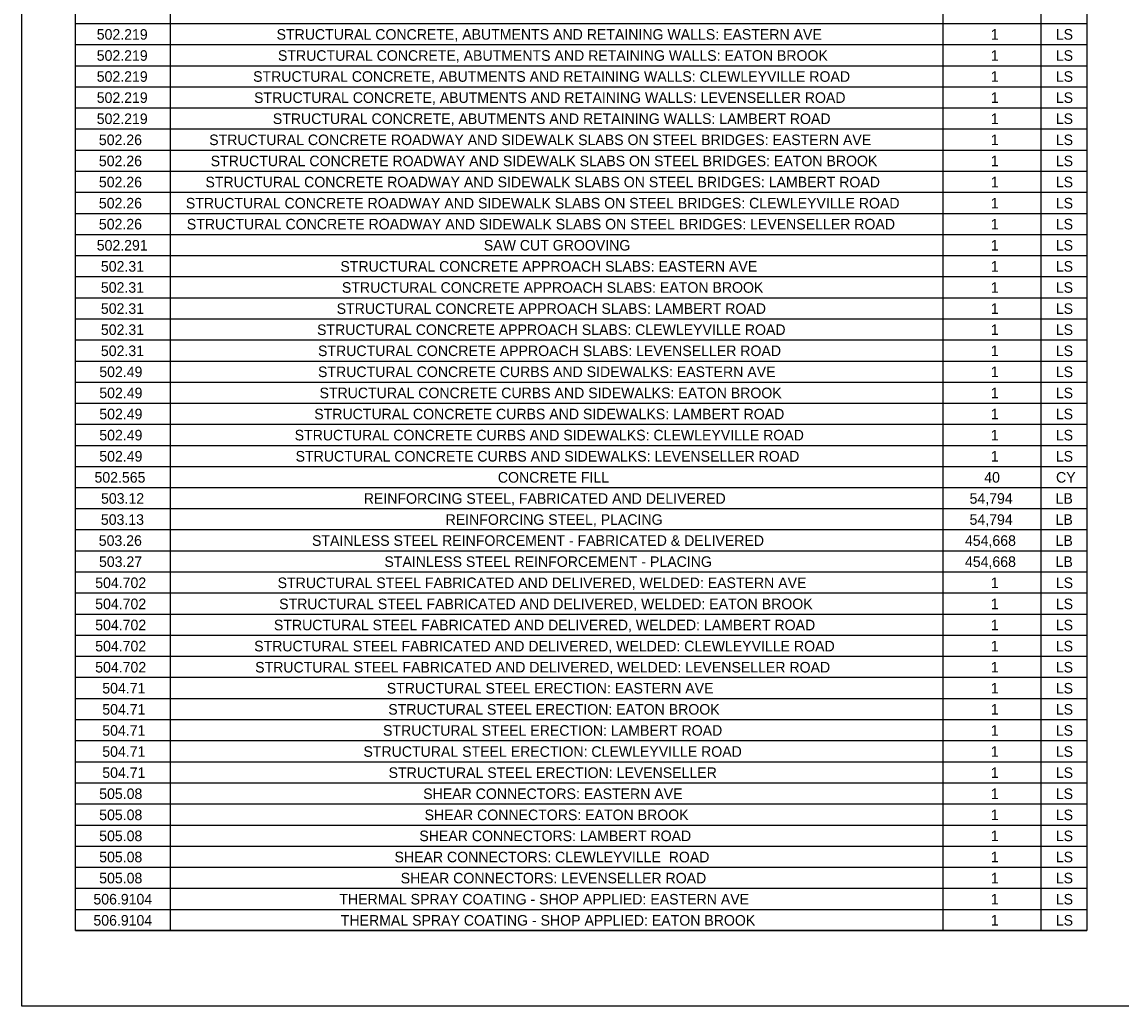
# Model space of a CAD drawing. Extents: x -18.7 to 5.6, y -2.7 to 4.
# Drawn here: x -17.663 to -16.637, y 2.172 to 3.09 of the extents above; entities that cross this region are included whole.
import ezdxf

# ---------------------------------------------------------------- set-up
doc = ezdxf.new("R2010")
doc.units = 0
doc.layers.add('ANNOTATION', color=7, linetype='Continuous')
doc.layers.add('BORDER', color=7, linetype='Continuous')

msp = doc.modelspace()

# ---------------------------------------------------------------- linework, layer by layer
at = {"layer": 'ANNOTATION'}
msp.add_lwpolyline([(-17.663, 4.0141), (-13.3075, 4.0141), (-13.3075, 2.1719), (-17.663, 2.1719)], close=True, dxfattribs=at)
at = {"layer": 'BORDER'}
for p, q in [((-17.5245, 3.9551), (-17.5245, 2.2424)), ((-16.8032, 3.9551), (-16.8032, 2.2424)), ((-16.7118, 3.9551), (-16.7118, 2.2424)), ((-17.613, 3.0889), (-16.6688, 3.0889)), ((-17.613, 3.0692), (-16.6688, 3.0692)), ((-17.613, 3.0495), (-16.6688, 3.0495)), ((-17.613, 3.0299), (-16.6688, 3.0299)), ((-17.613, 3.0102), (-16.6688, 3.0102)), ((-17.613, 2.9905), (-16.6688, 2.9905)), ((-17.613, 2.9708), (-16.6688, 2.9708)), ((-17.613, 2.9511), (-16.6688, 2.9511)), ((-17.613, 2.9314), (-16.6688, 2.9314)), ((-17.613, 2.9117), (-16.6688, 2.9117)), ((-17.613, 2.8921), (-16.6688, 2.8921)), ((-17.613, 2.8724), (-16.6688, 2.8724)), ((-17.613, 2.8527), (-16.6688, 2.8527)), ((-17.613, 2.833), (-16.6688, 2.833)), ((-17.613, 2.8133), (-16.6688, 2.8133)), ((-17.613, 2.7936), (-16.6688, 2.7936)), ((-17.613, 2.7739), (-16.6688, 2.7739)), ((-17.613, 2.7543), (-16.6688, 2.7543)), ((-17.613, 2.7346), (-16.6688, 2.7346)), ((-17.613, 2.7149), (-16.6688, 2.7149)), ((-17.613, 2.6952), (-16.6688, 2.6952)), ((-17.613, 2.6755), (-16.6688, 2.6755)), ((-17.613, 2.6558), (-16.6688, 2.6558)), ((-17.613, 2.6361), (-16.6688, 2.6361)), ((-17.613, 2.6165), (-16.6688, 2.6165)), ((-17.613, 2.5968), (-16.6688, 2.5968)), ((-17.613, 2.5771), (-16.6688, 2.5771)), ((-17.613, 2.5574), (-16.6688, 2.5574)), ((-17.613, 2.5377), (-16.6688, 2.5377)), ((-17.613, 2.518), (-16.6688, 2.518)), ((-17.613, 2.4983), (-16.6688, 2.4983)), ((-17.613, 2.4787), (-16.6688, 2.4787)), ((-17.613, 2.459), (-16.6688, 2.459)), ((-17.613, 2.4393), (-16.6688, 2.4393)), ((-17.613, 2.4196), (-16.6688, 2.4196)), ((-17.613, 2.3999), (-16.6688, 2.3999)), ((-17.613, 2.3802), (-16.6688, 2.3802)), ((-17.613, 2.3605), (-16.6688, 2.3605)), ((-17.613, 2.3408), (-16.6688, 2.3408)), ((-17.613, 2.3212), (-16.6688, 2.3212)), ((-17.613, 2.3015), (-16.6688, 2.3015)), ((-17.613, 2.2818), (-16.6688, 2.2818)), ((-17.613, 2.2621), (-16.6688, 2.2621)), ((-17.613, 2.2424), (-16.6688, 2.2424))]:
    msp.add_line(p, q, dxfattribs=at)
msp.add_lwpolyline([(-17.613, 3.9748), (-16.6688, 3.9748), (-16.6688, 2.2424), (-17.613, 2.2424)], close=True, dxfattribs=at)

# ---------------------------------------------------------------- texts
at = {"layer": 'ANNOTATION'}
for s, height, p in [('502.219', 0.00984, (-17.5932, 3.0738)), ('STRUCTURAL CONCRETE, ABUTMENTS AND RETAINING WALLS: EASTERN AVE', 0.009843, (-17.4253, 3.0738)), ('1', 0.00984, (-16.7585, 3.0738)), ('LS', 0.00984, (-16.6978, 3.0738)), ('502.219', 0.00984, (-17.5932, 3.0541)), ('STRUCTURAL CONCRETE, ABUTMENTS AND RETAINING WALLS: EATON BROOK', 0.009843, (-17.424, 3.0541)), ('1', 0.00984, (-16.7585, 3.0541)), ('LS', 0.00984, (-16.6978, 3.0541)), ('502.219', 0.00984, (-17.5932, 3.0345)), ('STRUCTURAL CONCRETE, ABUTMENTS AND RETAINING WALLS: CLEWLEYVILLE ROAD', 0.009843, (-17.4472, 3.0345)), ('1', 0.00984, (-16.7585, 3.0345)), ('LS', 0.00984, (-16.6978, 3.0345)), ('502.219', 0.00984, (-17.5932, 3.0148)), ('STRUCTURAL CONCRETE, ABUTMENTS AND RETAINING WALLS: LEVENSELLER ROAD', 0.009843, (-17.4463, 3.0148)), ('1', 0.00984, (-16.7585, 3.0148)), ('LS', 0.00984, (-16.6978, 3.0148)), ('502.219', 0.00984, (-17.5932, 2.9951)), ('STRUCTURAL CONCRETE, ABUTMENTS AND RETAINING WALLS: LAMBERT ROAD', 0.009843, (-17.4288, 2.9951)), ('1', 0.00984, (-16.7585, 2.9951)), ('LS', 0.00984, (-16.6978, 2.9951)), ('502.26', 0.00984, (-17.5912, 2.9754)), ('STRUCTURAL CONCRETE ROADWAY AND SIDEWALK SLABS ON STEEL BRIDGES: EASTERN AVE', 0.009843, (-17.4882, 2.9754)), ('1', 0.00984, (-16.7585, 2.9754)), ('LS', 0.00984, (-16.6978, 2.9754)), ('502.26', 0.00984, (-17.5912, 2.9557)), ('STRUCTURAL CONCRETE ROADWAY AND SIDEWALK SLABS ON STEEL BRIDGES: EATON BROOK', 0.009843, (-17.4868, 2.9557)), ('1', 0.00984, (-16.7585, 2.9557)), ('LS', 0.00984, (-16.6978, 2.9557)), ('502.26', 0.00984, (-17.5912, 2.936)), ('STRUCTURAL CONCRETE ROADWAY AND SIDEWALK SLABS ON STEEL BRIDGES: LAMBERT ROAD', 0.009843, (-17.4917, 2.936)), ('1', 0.00984, (-16.7585, 2.936)), ('LS', 0.00984, (-16.6978, 2.936)), ('502.26', 0.00984, (-17.5912, 2.9163)), ('STRUCTURAL CONCRETE ROADWAY AND SIDEWALK SLABS ON STEEL BRIDGES: CLEWLEYVILLE ROAD', 0.009843, (-17.51, 2.9163)), ('1', 0.00984, (-16.7585, 2.9163)), ('LS', 0.00984, (-16.6978, 2.9163)), ('502.26', 0.00984, (-17.5912, 2.8967)), ('STRUCTURAL CONCRETE ROADWAY AND SIDEWALK SLABS ON STEEL BRIDGES: LEVENSELLER ROAD', 0.009843, (-17.5091, 2.8967)), ('1', 0.00984, (-16.7585, 2.8967)), ('LS', 0.00984, (-16.6978, 2.8967)), ('502.291', 0.00984, (-17.5932, 2.877)), ('SAW CUT GROOVING', 0.009843, (-17.2318, 2.877)), ('1', 0.00984, (-16.7585, 2.877)), ('LS', 0.00984, (-16.6978, 2.877)), ('502.31', 0.00984, (-17.5893, 2.8573)), ('STRUCTURAL CONCRETE APPROACH SLABS: EASTERN AVE', 0.009843, (-17.3657, 2.8573)), ('1', 0.00984, (-16.7585, 2.8573)), ('LS', 0.00984, (-16.6978, 2.8573)), ('502.31', 0.00984, (-17.5893, 2.8376)), ('STRUCTURAL CONCRETE APPROACH SLABS: EATON BROOK', 0.009843, (-17.3643, 2.8376)), ('1', 0.00984, (-16.7585, 2.8376)), ('LS', 0.00984, (-16.6978, 2.8376)), ('502.31', 0.00984, (-17.5893, 2.8179)), ('STRUCTURAL CONCRETE APPROACH SLABS: LAMBERT ROAD', 0.009843, (-17.3692, 2.8179)), ('1', 0.00984, (-16.7585, 2.8179)), ('LS', 0.00984, (-16.6978, 2.8179)), ('502.31', 0.00984, (-17.5893, 2.7982)), ('STRUCTURAL CONCRETE APPROACH SLABS: CLEWLEYVILLE ROAD', 0.009843, (-17.3875, 2.7982)), ('1', 0.00984, (-16.7585, 2.7982)), ('LS', 0.00984, (-16.6978, 2.7982)), ('502.31', 0.00984, (-17.5893, 2.7785)), ('STRUCTURAL CONCRETE APPROACH SLABS: LEVENSELLER ROAD', 0.009843, (-17.3866, 2.7785)), ('1', 0.00984, (-16.7585, 2.7785)), ('LS', 0.00984, (-16.6978, 2.7785)), ('502.49', 0.00984, (-17.5908, 2.7589)), ('STRUCTURAL CONCRETE CURBS AND SIDEWALKS: EASTERN AVE', 0.009843, (-17.3866, 2.7589)), ('1', 0.00984, (-16.7585, 2.7589)), ('LS', 0.00984, (-16.6978, 2.7589)), ('502.49', 0.00984, (-17.5908, 2.7392)), ('STRUCTURAL CONCRETE CURBS AND SIDEWALKS: EATON BROOK', 0.009843, (-17.3852, 2.7392)), ('1', 0.00984, (-16.7585, 2.7392)), ('LS', 0.00984, (-16.6978, 2.7392)), ('502.49', 0.00984, (-17.5908, 2.7195)), ('STRUCTURAL CONCRETE CURBS AND SIDEWALKS: LAMBERT ROAD', 0.009843, (-17.3901, 2.7195)), ('LS', 0.00984, (-16.6978, 2.7195)), ('1', 0.00984, (-16.7585, 2.7195)), ('502.49', 0.00984, (-17.5908, 2.6998)), ('STRUCTURAL CONCRETE CURBS AND SIDEWALKS: CLEWLEYVILLE ROAD', 0.009843, (-17.4084, 2.6998)), ('1', 0.00984, (-16.7585, 2.6998)), ('LS', 0.00984, (-16.6978, 2.6998)), ('502.49', 0.00984, (-17.5908, 2.6801)), ('STRUCTURAL CONCRETE CURBS AND SIDEWALKS: LEVENSELLER ROAD', 0.009843, (-17.4075, 2.6801)), ('1', 0.00984, (-16.7585, 2.6801)), ('LS', 0.00984, (-16.6978, 2.6801)), ('502.565', 0.00984, (-17.5953, 2.6604)), ('CONCRETE FILL', 0.009843, (-17.2187, 2.6604)), ('40', 0.00984, (-16.7646, 2.6604)), ('CY', 0.00984, (-16.6976, 2.6604)), ('503.12', 0.00984, (-17.5892, 2.6407)), ('REINFORCING STEEL, FABRICATED AND DELIVERED', 0.009843, (-17.3439, 2.6407)), ('54,794', 0.00984, (-16.7783, 2.6407)), ('LB', 0.00984, (-16.698, 2.6407)), ('503.13', 0.00984, (-17.5893, 2.621)), ('REINFORCING STEEL, PLACING', 0.009843, (-17.2675, 2.621)), ('54,794', 0.00984, (-16.7783, 2.621)), ('LB', 0.00984, (-16.698, 2.621)), ('503.26', 0.00984, (-17.5913, 2.6014)), ('STAINLESS STEEL REINFORCEMENT - FABRICATED & DELIVERED', 0.009843, (-17.3922, 2.6014)), ('454,668', 0.00984, (-16.7826, 2.6014)), ('LB', 0.00984, (-16.698, 2.6014)), ('503.27', 0.00984, (-17.5911, 2.5817)), ('STAINLESS STEEL REINFORCEMENT - PLACING', 0.009843, (-17.3246, 2.5817)), ('454,668', 0.00984, (-16.7826, 2.5817)), ('LB', 0.00984, (-16.698, 2.5817)), ('504.702', 0.00984, (-17.5946, 2.562)), ('STRUCTURAL STEEL FABRICATED AND DELIVERED, WELDED: EASTERN AVE', 0.009843, (-17.4243, 2.562)), ('1', 0.00984, (-16.7585, 2.562)), ('LS', 0.00984, (-16.6978, 2.562)), ('504.702', 0.00984, (-17.5946, 2.5423)), ('STRUCTURAL STEEL FABRICATED AND DELIVERED, WELDED: EATON BROOK', 0.009843, (-17.4229, 2.5423)), ('1', 0.00984, (-16.7585, 2.5423)), ('LS', 0.00984, (-16.6978, 2.5423)), ('504.702', 0.00984, (-17.5946, 2.5226)), ('STRUCTURAL STEEL FABRICATED AND DELIVERED, WELDED: LAMBERT ROAD', 0.009843, (-17.4278, 2.5226)), ('1', 0.00984, (-16.7585, 2.5226)), ('LS', 0.00984, (-16.6978, 2.5226)), ('504.702', 0.00984, (-17.5946, 2.5029)), ('STRUCTURAL STEEL FABRICATED AND DELIVERED, WELDED: CLEWLEYVILLE ROAD', 0.009843, (-17.4462, 2.5029)), ('1', 0.00984, (-16.7585, 2.5029)), ('LS', 0.00984, (-16.6978, 2.5029)), ('504.702', 0.00984, (-17.5946, 2.4832)), ('STRUCTURAL STEEL FABRICATED AND DELIVERED, WELDED: LEVENSELLER ROAD', 0.009843, (-17.4453, 2.4832)), ('1', 0.00984, (-16.7585, 2.4832)), ('LS', 0.00984, (-16.6978, 2.4832)), ('504.71', 0.00984, (-17.588, 2.4636)), ('STRUCTURAL STEEL ERECTION: EASTERN AVE', 0.009843, (-17.3224, 2.4636)), ('1', 0.00984, (-16.7585, 2.4636)), ('LS', 0.00984, (-16.6978, 2.4636)), ('504.71', 0.00984, (-17.588, 2.4439)), ('STRUCTURAL STEEL ERECTION: EATON BROOK', 0.009843, (-17.321, 2.4439)), ('1', 0.00984, (-16.7585, 2.4439)), ('LS', 0.00984, (-16.6978, 2.4439)), ('504.71', 0.00984, (-17.588, 2.4242)), ('STRUCTURAL STEEL ERECTION: LAMBERT ROAD', 0.009843, (-17.3259, 2.4242)), ('1', 0.00984, (-16.7585, 2.4242)), ('LS', 0.00984, (-16.6978, 2.4242)), ('504.71', 0.00984, (-17.588, 2.4045)), ('STRUCTURAL STEEL ERECTION: CLEWLEYVILLE ROAD', 0.009843, (-17.3442, 2.4045)), ('1', 0.00984, (-16.7585, 2.4045)), ('LS', 0.00984, (-16.6978, 2.4045)), ('504.71', 0.00984, (-17.588, 2.3848)), ('STRUCTURAL STEEL ERECTION: LEVENSELLER', 0.009843, (-17.3207, 2.3848)), ('1', 0.00984, (-16.7585, 2.3848)), ('LS', 0.00984, (-16.6978, 2.3848)), ('505.08', 0.00984, (-17.5909, 2.3651)), ('SHEAR CONNECTORS: EASTERN AVE', 0.009843, (-17.2884, 2.3651)), ('1', 0.00984, (-16.7585, 2.3651)), ('LS', 0.00984, (-16.6978, 2.3651)), ('505.08', 0.00984, (-17.5909, 2.3454)), ('SHEAR CONNECTORS: EATON BROOK', 0.009843, (-17.2871, 2.3454)), ('1', 0.00984, (-16.7585, 2.3454)), ('LS', 0.00984, (-16.6978, 2.3454)), ('505.08', 0.00984, (-17.5909, 2.3258)), ('SHEAR CONNECTORS: LAMBERT ROAD', 0.009843, (-17.292, 2.3258)), ('1', 0.00984, (-16.7585, 2.3258)), ('LS', 0.00984, (-16.6978, 2.3258)), ('505.08', 0.00984, (-17.5909, 2.3061)), ('SHEAR CONNECTORS: CLEWLEYVILLE  ROAD', 0.009843, (-17.3152, 2.3061)), ('1', 0.00984, (-16.7585, 2.3061)), ('LS', 0.00984, (-16.6978, 2.3061)), ('505.08', 0.00984, (-17.5909, 2.2864)), ('SHEAR CONNECTORS: LEVENSELLER ROAD', 0.009843, (-17.3094, 2.2864)), ('1', 0.00984, (-16.7585, 2.2864)), ('LS', 0.00984, (-16.6978, 2.2864)), ('506.9104', 0.00984, (-17.5963, 2.2667)), ('THERMAL SPRAY COATING - SHOP APPLIED: EASTERN AVE', 0.009843, (-17.3667, 2.2667)), ('1', 0.00984, (-16.7585, 2.2667)), ('LS', 0.00984, (-16.6978, 2.2667)), ('506.9104', 0.00984, (-17.5963, 2.247)), ('THERMAL SPRAY COATING - SHOP APPLIED: EATON BROOK', 0.009843, (-17.3653, 2.247)), ('1', 0.00984, (-16.7585, 2.247)), ('LS', 0.00984, (-16.6978, 2.247))]:
    msp.add_text(s, height=height, dxfattribs=at).set_placement(p)

doc.saveas('drawing.dxf')
